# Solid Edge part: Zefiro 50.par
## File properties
Title: Zefiro 50
Author: DESYS
Template: Normal.par
Last saved by: i.fialdini
Revision: 32
Application: Solid Edge
Tipo di contenuto documento: 0
Precisione: 0,990
Document Number: 8207
Revision: 0
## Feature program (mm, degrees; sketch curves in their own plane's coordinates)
lofted protrusion "unnamed LoftedProtrusion 1"
sketch for "unnamed Cutout 1" plane through (0, 0, 0) normal (1, 0, 0) x-axis (0, 1, 0)
  arc centre (0, 403.1295) radius 473.8295 from (-249, 0) to (249, 0) ccw
extrude "unnamed Cutout 1" cut through
thinwall "unnamed Thinwall 1"
fillet "Rotondo_1" radius 5
fillet "Rotondo_2" radius 50
sketch for "ExtrudedProtrusion_1" plane through (0, 0, -166) normal (0, 0, -1) x-axis (0, 1, 0)
extrude "ExtrudedProtrusion_1" add finite 20 along +normal
sketch for "ExtrudedCutout_2" plane through (0, 0, -186) normal (0, 0, -1) x-axis (0, 1, 0)
  bspline degree 3 poles (78.5, 0) (78.5, 4.3484) (77.9677, 8.9771) (75.4059, 18.625) (73.3678, 23.6507) (68.871, 31.1661) (67.1349, 33.6629) (63.1633, 38.5563) (60.9279, 40.953) (55.9699, 45.5444) (53.2474, 47.7391) (47.3673, 51.8237) (44.2097, 53.7136) (37.5532, 57.0996) (34.0537, 58.5961) (26.8352, 61.1329) (23.1161, 62.1734) (15.5949, 63.7732) (11.7927, 64.3327) (4.2395, 64.9813) (0.4885, 65.0705) (-10.5195, 64.6996) (-17.5064, 63.59) (-30.1906, 60.2077) (-35.8925, 57.9453) (-45.8726, 52.8699) (-50.8014, 49.7202) (-59.9157, 42.1889) (-64.091, 37.8048) (-71.0454, 28.0794) (-73.8151, 22.7419) (-77.5432, 11.6018) (-78.5017, 5.7991) (-78.5017, -5.7991) (-77.5432, -11.6018) (-73.8151, -22.7419) (-71.0454, -28.0794) (-64.091, -37.8048) (-59.9157, -42.1889) (-50.8014, -49.7202) (-45.8726, -52.8699) (-35.8925, -57.9453) (-30.1906, -60.2077) (-17.5064, -63.59) (-10.5195, -64.6996) (0.4885, -65.0705) (4.2395, -64.9813) (11.7927, -64.3327) (15.5949, -63.7732) (23.1161, -62.1734) (26.8352, -61.1329) (34.0537, -58.5961) (37.5532, -57.0996) (44.2097, -53.7136) (47.3673, -51.8237) (53.2474, -47.7391) (55.9699, -45.5444) (60.9279, -40.953) (63.1633, -38.5563) (67.1349, -33.6629) (68.871, -31.1661) (73.3678, -23.6507) (75.4059, -18.625) (77.9677, -8.9771) (78.5, -4.3477) (78.5, 0) knots 0 0.0417 0.0833 0.1042 0.125 0.1458 0.1667 0.1875 0.2083 0.2292 0.25 0.2917 0.3333 0.375 0.4167 0.4583 0.5 0.5417 0.5833 0.625 0.6667 0.7083 0.75 0.7708 0.7917 0.8125 0.8333 0.8542 0.875 0.8958 0.9167 0.9583 1 multiplicities 4 2 2 2 2 2 2 2 2 2 2 2 2 2 2 2 2 2 2 2 2 2 2 2 2 2 2 2 2 2 2 2 4
extrude "ExtrudedCutout_2" cut finite 15 along -normal
sketch for "ExtrudedProtrusion_2" plane through (-0.0026, 0, -171) normal (0, 0, -1) x-axis (0, 1, 0)
  circle centre (0, 0.0026) radius 32.5
extrude "ExtrudedProtrusion_2" add finite 15 along +normal
sketch for "Foro_1" plane through (0, 0, -186) normal (0, 0, -1) x-axis (0, 1, 0)
  hole centre (0, 0) bore radius 25
hole "Foro_1" diameter 50 through
fillet "Rotondo_4" radius 3
fillet "Rotondo_5" radius 10
fillet "Rotondo_6" radius 15  VertexRadius1 = 15 mm; VertexRadius2 = 15 mm; VertexRadius3 = 99 mm; VertexRadius4 = 99 mm
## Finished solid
Body 1: solid body, 22 faces, 33 edges, 13 vertices.
  Faces by surface: spline 5, blend 4, plane 4, swept 3, torus 3, cylinder 2, offset 1
  Edges by curve: curve on surface 12, intersection 11, circle 7, ellipse 2, spline 1
Bounding box of the edges (mm; curved faces can reach further): 362.139 x 491.344 x 179.631, from (-180.9358, -245.6598, -186) to (181.203, 245.6843, -6.3692).
Cylindrical faces by radius (mm): R25 x1, R32.5 x1
Toroidal faces (ring radius, tube radius in mm): R29.5 r3 x1, R35 r10 x1, R35.5 r3 x1
Planar faces by outward normal: +z 1, -z 3
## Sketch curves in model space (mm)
arc centre (39.297, 0, -28.8317) radius 150 from (186.5, 0, 0) through (170.233, 0, -102.0148) to (100, 0, -166)
arc centre (-39.297, 0, -28.8317) radius 150 from (-186.5, 0, 0) through (-170.233, 0, -102.0148) to (-100, 0, -166)
arc centre (0, 6.2657, 59.8336) radius 250 from (0, 249, 0) through (0, 199.9368, -98.2534) to (0, 113.5, -166)
arc centre (0, -6.2657, 59.8336) radius 250 from (0, -249, 0) through (0, -199.9368, -98.2534) to (0, -113.5, -166)
ellipse centre (0, 0, -166) radii 113.5, 100
ellipse centre (0, 0, 0) radii 249, 186.5
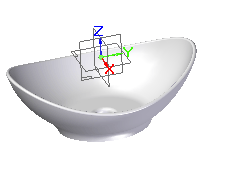
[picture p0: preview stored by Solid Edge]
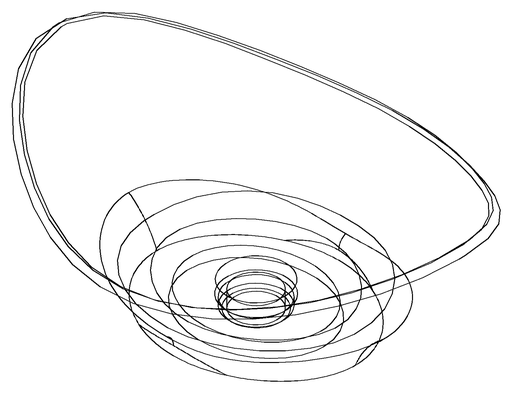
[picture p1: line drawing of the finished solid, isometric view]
